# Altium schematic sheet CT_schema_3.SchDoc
size 573 x 363 mm
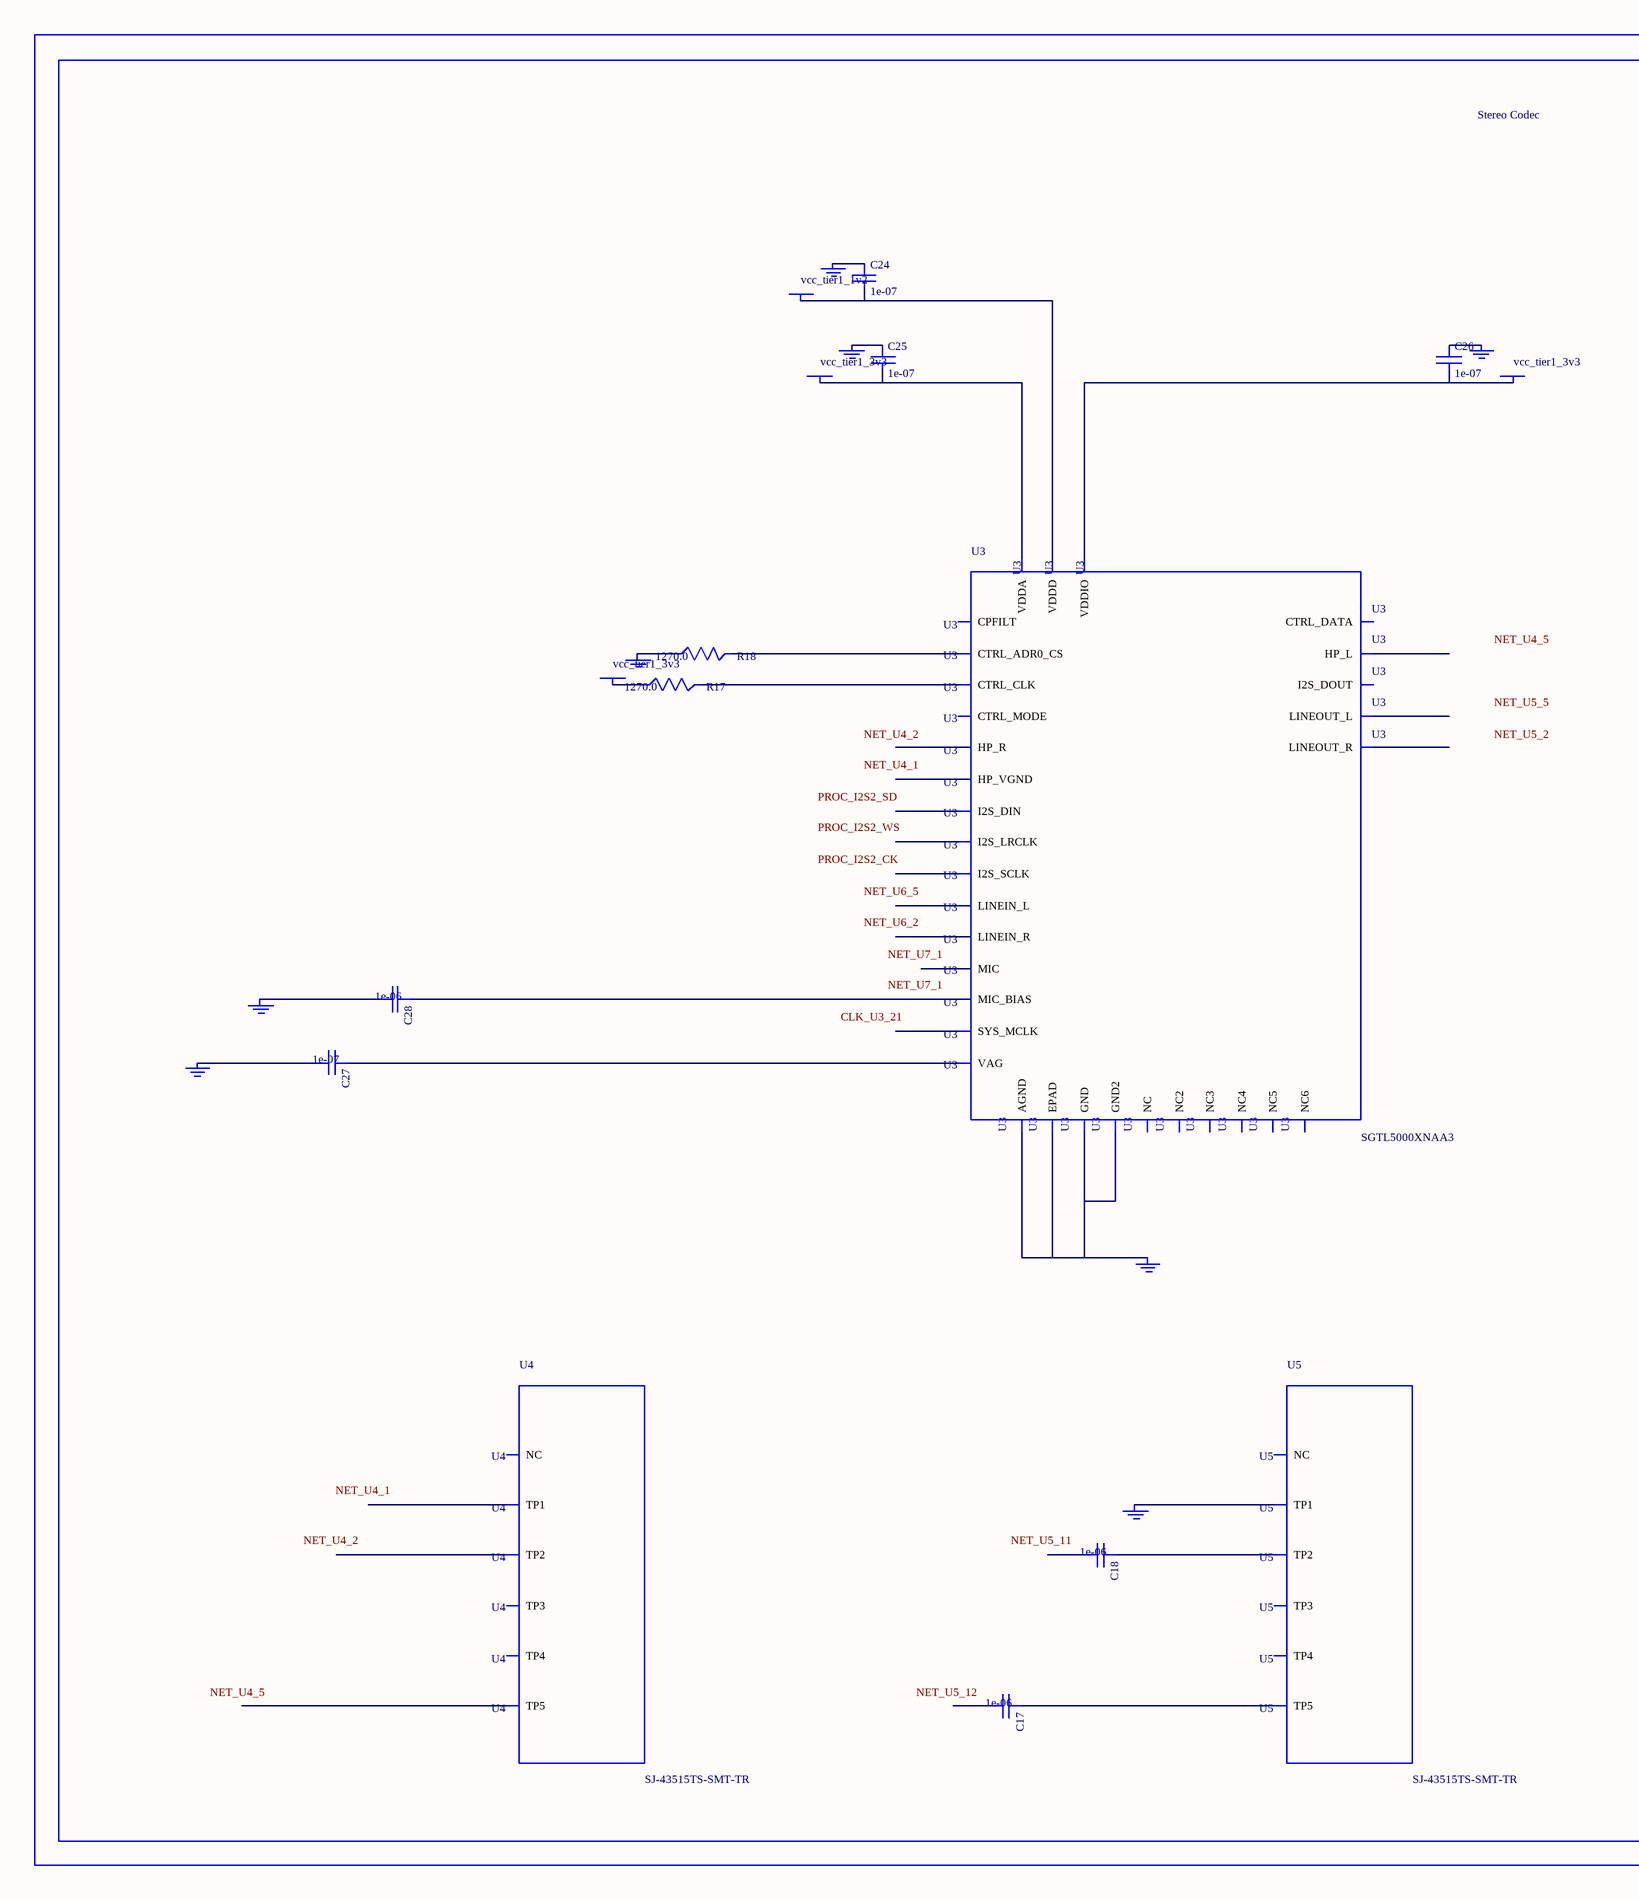
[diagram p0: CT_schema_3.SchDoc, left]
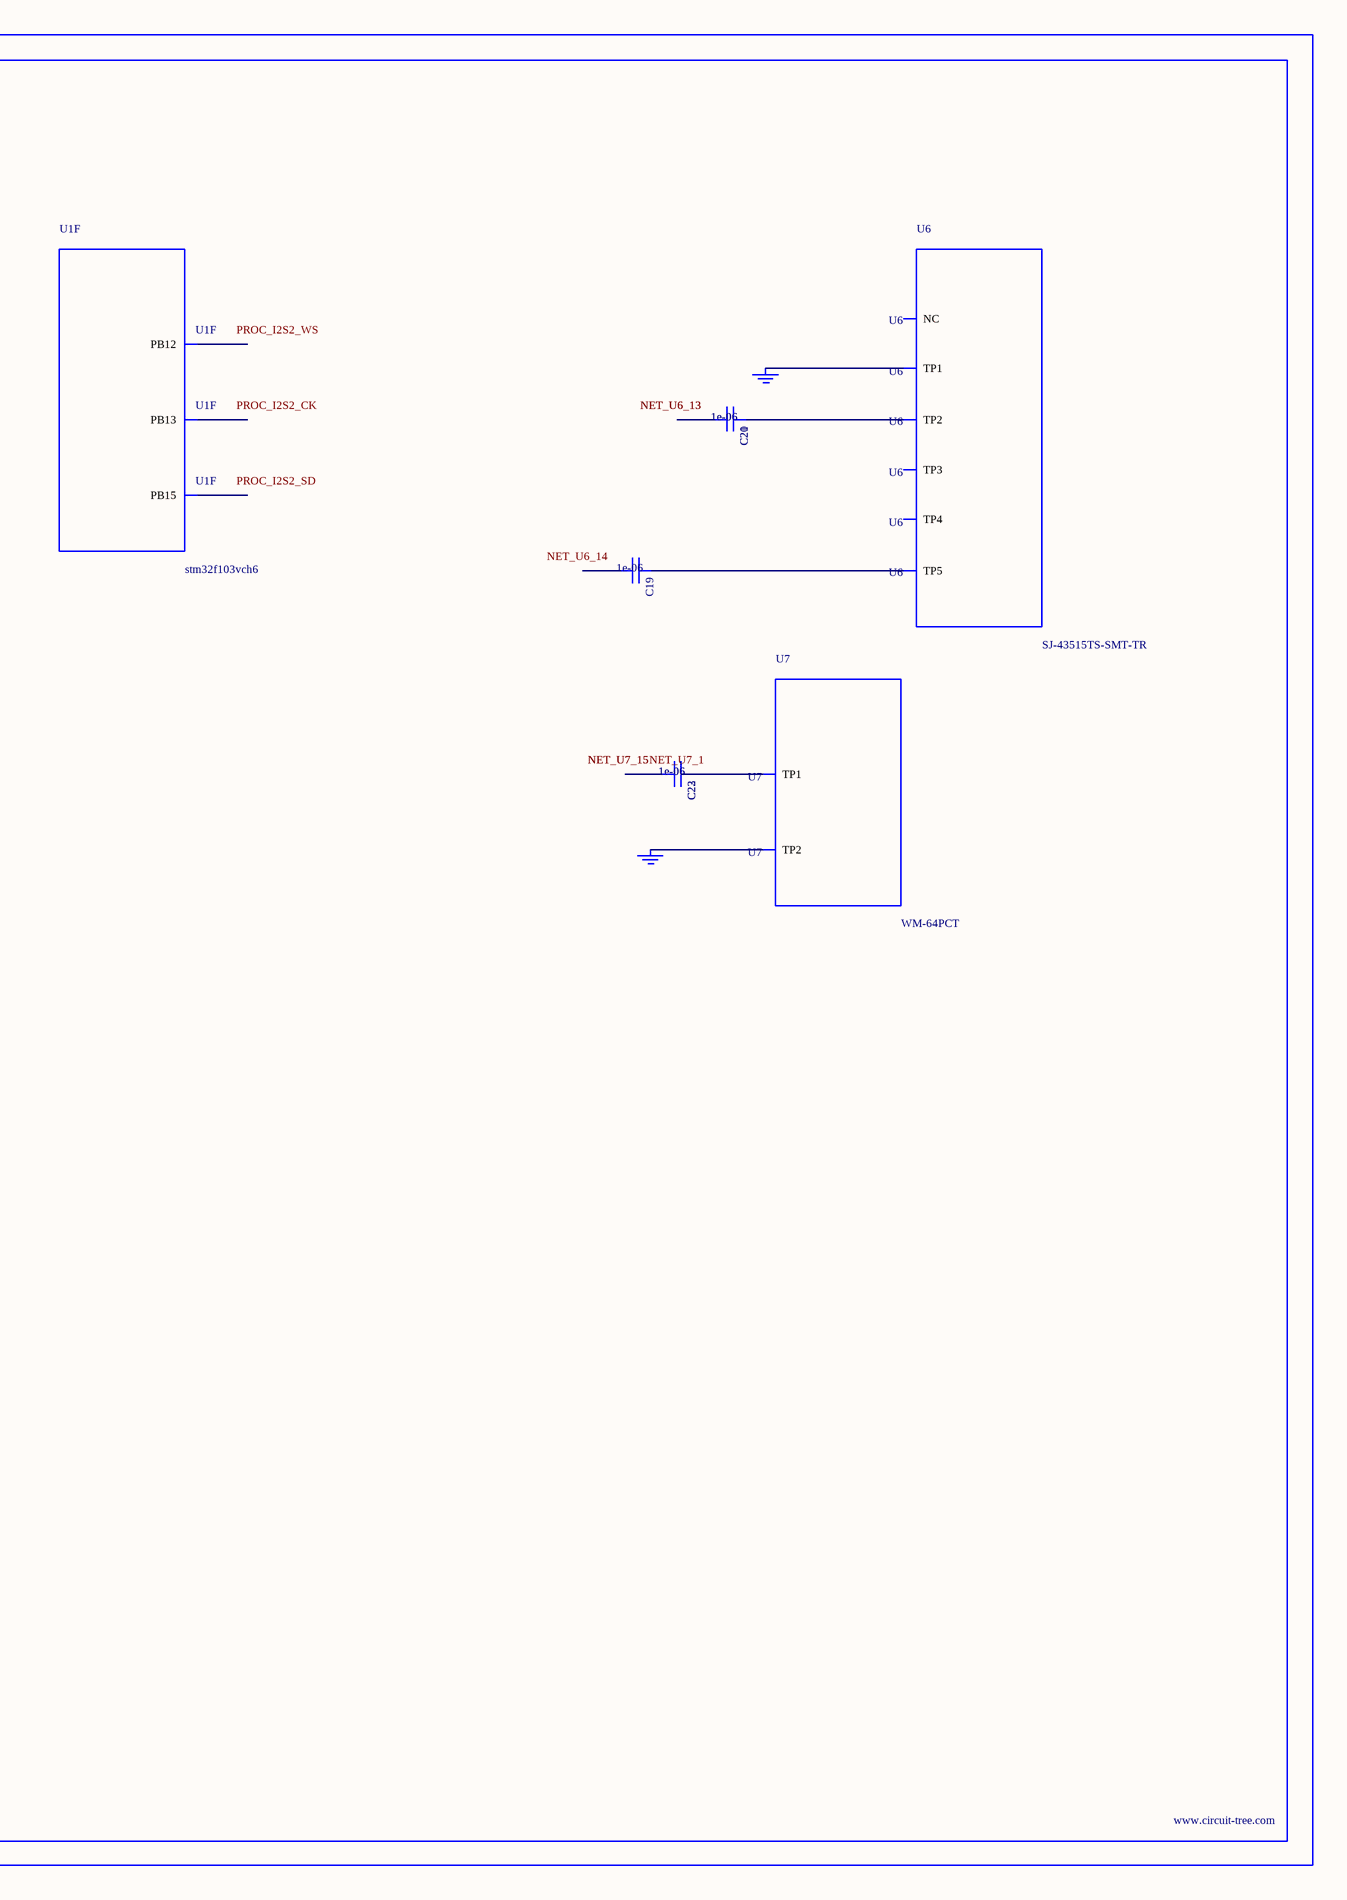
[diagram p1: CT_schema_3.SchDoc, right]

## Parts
BORDER2  (no value)
C17  1e-06  [C0603]
C18  1e-06  [C0603]
C19  1e-06  [C0603]
C20  1e-06  [C0603]
C21  1e-06  [C0603]
C22  1e-06  [C0603]
C23  1e-06  [C0603]
C24  1e-07  [C0402]
C25  1e-07  [C0402]
C26  1e-07  [C0402]
C27  1e-07  [C0402]
C28  1e-06  [C0603]
GND_INSTANCE_2_0  (no value)
GND_INSTANCE_2_1  (no value)
GND_INSTANCE_2_2  (no value)
GND_INSTANCE_2_3  (no value)
GND_INSTANCE_2_4  (no value)
GND_INSTANCE_2_5  (no value)
GND_INSTANCE_2_6  (no value)
GND_INSTANCE_2_7  (no value)
GND_INSTANCE_2_8  (no value)
GND_INSTANCE_2_9  (no value)
GND_INSTANCE_2_10  (no value)
POWER_INSTANCE_2_0  vcc_tier1_3v3
POWER_INSTANCE_2_1  vcc_tier1_3v3
POWER_INSTANCE_2_2  vcc_tier1_3v3
POWER_INSTANCE_2_3  vcc_tier1_1v2
R17  1270.0  [R0603]
R18  1270.0  [R0603]
U1  stm32f103vch6  [LFBGA100]  (part F of 8)
U3  SGTL5000XNAA3  [QFN-32]
U4  SJ-43515TS-SMT-TR  [SJ-43515TS-SMT-TR]
U5  SJ-43515TS-SMT-TR  [SJ-43515TS-SMT-TR]
U6  SJ-43515TS-SMT-TR  [SJ-43515TS-SMT-TR]
U7  WM-64PCT  [WM-64PC]

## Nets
NetC17_1: C17.1 U5.5(TP5)
NetC18_1: C18.1 U5.2(TP2)
NetC19_1: C19.1 U6.5(TP5)
NetC20_1: C20.1 C21.1 U6.2(TP2)
NetC20_2: C20.2 C21.2
NetC22_1: C22.1 C23.1 U7.1(TP1)
NetC22_2: C22.2 C23.2
NetC24_1: C24.1 GND_INSTANCE_2_5.0(GND)
NetC24_2: C24.2 POWER_INSTANCE_2_3.0(PWR) U3.30(VDDD)
NetC25_1: C25.1 GND_INSTANCE_2_1.0(GND)
NetC25_2: C25.2 POWER_INSTANCE_2_0.0(PWR) U3.5(VDDA)
NetC26_1: C26.1 GND_INSTANCE_2_4.0(GND)
NetC26_2: C26.2 POWER_INSTANCE_2_1.0(PWR) U3.20(VDDIO)
NetC27_1: C27.1 U3.10(VAG)
NetC27_2: C27.2 GND_INSTANCE_2_2.0(GND)
NetC28_1: C28.1 U3.16(MIC_BIAS)
NetC28_2: C28.2 GND_INSTANCE_2_3.0(GND)
NetGND_INSTANCE_2_0_0: GND_INSTANCE_2_0.0(GND) U3.1(GND) U3.3(GND2) U3.7(AGND) U3.EXP(EPAD)
NetGND_INSTANCE_2_6_0: GND_INSTANCE_2_6.0(GND) R18.1
NetGND_INSTANCE_2_7_0: GND_INSTANCE_2_7.0(GND) U5.1(TP1)
NetGND_INSTANCE_2_8_0: GND_INSTANCE_2_8.0(GND) GND_INSTANCE_2_9.0(GND) U6.1(TP1)
NetGND_INSTANCE_2_10_0: GND_INSTANCE_2_10.0(GND) U7.2(TP2)
NetPOWER_INSTANCE_2_2_0: POWER_INSTANCE_2_2.0(PWR) R17.1
NetR17_2: R17.2 U3.29(CTRL_CLK)
NetR18_2: R18.2 U3.31(CTRL_ADR0_CS)

Not connected (* = marked no-connect by the designer): C17 2; C18 2; C19 2; U1 G8(PB15) J8(PB13) K8(PB12); U3 2(HP_R) 4(HP_VGND) 6(HP_L) 8(NC) 9(NC2) 11(LINEOUT_R) 12(LINEOUT_L) 13(LINEIN_R) 14(LINEIN_L) 15(MIC) 17(NC3) 18(CPFILT) 19(NC4) 21(SYS_MCLK) 22(NC5) 23(I2S_LRCLK) 24(I2S_SCLK) 25(I2S_DOUT) 26(I2S_DIN) 27(CTRL_DATA) 28(NC6) 32(CTRL_MODE); U4 1(TP1) 2(TP2) 3(TP3) 4(TP4) 5(TP5) 6(NC); U5 3(TP3) 4(TP4) 6(NC); U6 3(TP3) 4(TP4) 6(NC)

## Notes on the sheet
- Labels drawn without touching a wire or pin: CLK_U3_21, NET_U4_1, NET_U4_2, NET_U4_5, NET_U5_2, NET_U5_5, NET_U5_11, NET_U5_12, NET_U6_2, NET_U6_5, NET_U6_14, NET_U7_1, PROC_I2S2_CK, PROC_I2S2_SD, PROC_I2S2_WS

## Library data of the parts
BORDER2 = BORDER_PAGE2
C17-C23 C28 = C0603C105K3RACTU
C24-C27 = C0402C104K3RACTU
GND_INSTANCE_2_0-GND_INSTANCE_2_10 = GND
POWER_INSTANCE_2_0-POWER_INSTANCE_2_3 = PWR
R17 R18 = RC0603FR-071K27L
